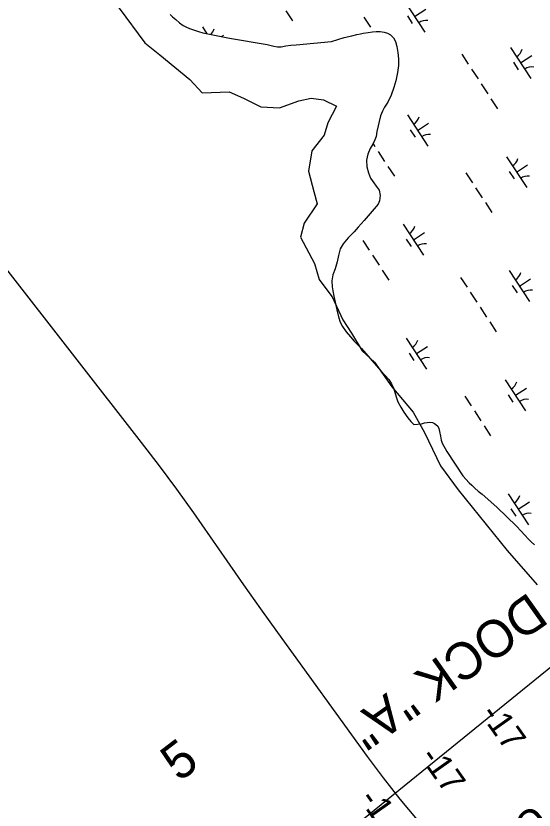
# Model space of a CAD drawing. Extents: x 3945642 to 3966284, y 206476 to 228921.
# Drawn here: x 3954881 to 3955580, y 219055 to 220127 of the extents above; entities that cross this region are included whole.
import ezdxf

# ---------------------------------------------------------------- set-up
doc = ezdxf.new("R2010")
doc.units = 0
for name, color, linetype in [('V-CHAN-NAID', 7, 'Continuous'), ('V-RIVR-EDGE', 7, 'Continuous'), ('V-RIVR-IDEN', 7, 'Continuous'), ('V-RIVR-RANG', 7, 'Continuous'), ('V-TOPO-MINR', 7, 'Continuous'), ('V-UTIL-IDEN', 7, 'Continuous'), ('V-UTIL-LINE', 7, 'Continuous'), ('V-WETL-SWMP', 7, 'Continuous')]:
    doc.layers.add(name, color=color, linetype=linetype)

msp = doc.modelspace()

# ---------------------------------------------------------------- linework, layer by layer
at = {"layer": 'V-RIVR-EDGE'}
msp.add_lwpolyline([(3954881.3, 220324.3), (3955054.6, 220090.4), (3955074.8, 220073.8), (3955115.2, 220040.5), (3955131.8, 220022.7), (3955168.6, 220023.9), (3955187.6, 220015.6), (3955211.3, 220003.7), (3955236.3, 220002.5), (3955262.4, 220012), (3955279, 220015.6), (3955295.6, 220013.2), (3955313.4, 220004.9), (3955301.6, 219982.4), (3955296.8, 219965.7), (3955280.2, 219944.4), (3955275.5, 219917.1), (3955282.6, 219889.8), (3955287.3, 219873.1), (3955269.5, 219847), (3955264.8, 219828), (3955283.8, 219792.4), (3955289.7, 219771), (3955300.4, 219756.8), (3955307.5, 219747.3), (3955321.8, 219716.4), (3955333.6, 219698.6), (3955347.9, 219674.9), (3955364.5, 219659.4), (3955388.2, 219626.2), (3955416.7, 219591.8), (3955432.2, 219564.5), (3955453.5, 219519.4), (3955477.3, 219487.3), (3955543.8, 219405.4), (3955584.1, 219359.1)], dxfattribs=at)
at = {"layer": 'V-TOPO-MINR'}
msp.add_lwpolyline([(3954493.5, 220264.9), (3955049.9, 219551), (3955073.9, 219519.7), (3955097.4, 219488.1), (3955120.3, 219456.1), (3955142.8, 219423.8), (3955165.2, 219391.3), (3955187.7, 219359), (3955210.6, 219326.8), (3955233.5, 219294.8), (3955354.8, 219127.6), (3955376.5, 219098.6), (3955398.9, 219070), (3955422.1, 219042.1)], dxfattribs=at)
at = {"layer": 'V-UTIL-LINE'}
msp.add_line((3954671.9, 218495), (3955749.6, 219367.2), dxfattribs=at)
at = {"layer": 'V-WETL-SWMP'}
for p, q in [((3955405.1, 220146.6), (3955432.5, 220104.7)), ((3955088.9, 220128.3), (3955092, 220125.3)), ((3955245.1, 220133.4), (3955253.9, 220120)), ((3955418.8, 220125.6), (3955433.8, 220135.5)), ((3955092, 220125.3), (3955096.4, 220121.5)), ((3955096.4, 220121.5), (3955101.6, 220117.3)), ((3955350.4, 220124.7), (3955359.1, 220111.3)), ((3955409, 220126.4), (3955415.6, 220116.4)), ((3955101.6, 220117.3), (3955106.4, 220113.7)), ((3955106.4, 220113.7), (3955110.1, 220111.7)), ((3955110.1, 220111.7), (3955114.9, 220109.6)), ((3955114.9, 220109.6), (3955120.5, 220107.5)), ((3955120.5, 220107.5), (3955126.9, 220105.4)), ((3955132.3, 220111.6), (3955138.3, 220102.5)), ((3955126.9, 220105.4), (3955132.8, 220103.6)), ((3955132.8, 220103.6), (3955168.9, 220096.4)), ((3955158, 220098.6), (3955161.1, 220100.6)), ((3955168.9, 220096.4), (3955219.8, 220087.9)), ((3955306.7, 220092), (3955323.7, 220097.2)), ((3955323.7, 220097.2), (3955334, 220099.6)), ((3955334, 220099.6), (3955340.6, 220101.3)), ((3955340.6, 220101.3), (3955345.8, 220102.5)), ((3955345.8, 220102.5), (3955349.5, 220103.1)), ((3955349.5, 220103.1), (3955355.9, 220103.9)), ((3955355.9, 220103.9), (3955361.8, 220104.8)), ((3955361.8, 220104.8), (3955367, 220105.3)), ((3955367, 220105.3), (3955372.2, 220105.4)), ((3955372.2, 220105.4), (3955377.8, 220104.7)), ((3955377.8, 220104.7), (3955382.3, 220103.2)), ((3955382.3, 220103.2), (3955386.2, 220100.9)), ((3955386.2, 220100.9), (3955390.1, 220096.9)), ((3955390.1, 220096.9), (3955392.8, 220091.8)), ((3955219.8, 220087.9), (3955228.6, 220085.5)), ((3955228.6, 220085.5), (3955233.9, 220084.8)), ((3955238.7, 220085), (3955244.9, 220086)), ((3955244.9, 220086), (3955251.5, 220087)), ((3955251.5, 220087), (3955258.7, 220087.7)), ((3955258.7, 220087.7), (3955306.7, 220092)), ((3955392.8, 220091.8), (3955394.8, 220085.2)), ((3955233.9, 220084.8), (3955238.7, 220085)), ((3955394.8, 220085.2), (3955396.2, 220077)), ((3955396.2, 220077), (3955397, 220068.7)), ((3955482.3, 220074.9), (3955491.1, 220061.5)), ((3955548.1, 220084), (3955575.5, 220042.2)), ((3955397, 220068.7), (3955396.8, 220059.6)), ((3955561.8, 220063.1), (3955576.9, 220073)), ((3955396.8, 220059.6), (3955395.5, 220050)), ((3955495.5, 220054.8), (3955504.3, 220041.4)), ((3955552.1, 220063.9), (3955558.7, 220053.9)), ((3955395.5, 220050), (3955393.3, 220039)), ((3955393.3, 220039), (3955390.8, 220030.1)), ((3955508.6, 220034.7), (3955517.4, 220021.4)), ((3955390.8, 220030.1), (3955387.2, 220019.5)), ((3955387.2, 220019.5), (3955382.6, 220010.2)), ((3955521.8, 220014.7), (3955530.6, 220001.3)), ((3955378, 220003.2), (3955375.2, 219998.1)), ((3955382.6, 220010.2), (3955378, 220003.2)), ((3955372.9, 219991.8), (3955367.7, 219970.4)), ((3955375.2, 219998.1), (3955372.9, 219991.8)), ((3955409, 219992.9), (3955436.4, 219951)), ((3955422.7, 219971.9), (3955437.7, 219981.8)), ((3955367.7, 219970.4), (3955366.8, 219963.7)), ((3955412.9, 219972.7), (3955419.5, 219962.7)), ((3955365.2, 219959.1), (3955362.3, 219953.7)), ((3955366.8, 219963.7), (3955365.2, 219959.1)), ((3955358.9, 219947.5), (3955355.4, 219940.2)), ((3955362.3, 219953.7), (3955358.9, 219947.5)), ((3955362.6, 219954.2), (3955365.1, 219950.3)), ((3955355.4, 219940.2), (3955353.8, 219932)), ((3955369.5, 219943.6), (3955378.3, 219930.2)), ((3955542.6, 219936.6), (3955570, 219894.8)), ((3955353.8, 219932), (3955354.4, 219922.9)), ((3955556.3, 219915.7), (3955571.3, 219925.6)), ((3955354.4, 219922.9), (3955356.5, 219914.9)), ((3955356.5, 219914.9), (3955359.4, 219907.8)), ((3955382.7, 219923.5), (3955391.4, 219910.1)), ((3955487.9, 219914.8), (3955496.7, 219901.4)), ((3955546.5, 219916.5), (3955553.1, 219906.5)), ((3955359.4, 219907.8), (3955363.5, 219901.1)), ((3955363.5, 219901.1), (3955366.8, 219896.8)), ((3955366.8, 219896.8), (3955370.8, 219891.2)), ((3955501, 219894.7), (3955509.8, 219881.3)), ((3955370.8, 219891.2), (3955372.2, 219884.4)), ((3955372.2, 219884.4), (3955371.5, 219876.9)), ((3955369.6, 219872.4), (3955350.5, 219850.6)), ((3955371.5, 219876.9), (3955369.6, 219872.4)), ((3955514.2, 219874.6), (3955523, 219861.3)), ((3955350.5, 219850.6), (3955342.7, 219841.6)), ((3955342.7, 219841.6), (3955337.3, 219835.1)), ((3955403.4, 219845.5), (3955430.8, 219803.7)), ((3955337.3, 219835.1), (3955329.2, 219827)), ((3955417.1, 219824.6), (3955432.2, 219834.4)), ((3955322.1, 219819.2), (3955318.3, 219812.2)), ((3955329.2, 219827), (3955322.1, 219819.2)), ((3955348.7, 219823.6), (3955357.5, 219810.3)), ((3955407.4, 219825.4), (3955414, 219815.3)), ((3955318.3, 219812.2), (3955316, 219803.1)), ((3955316, 219803.1), (3955314.4, 219794.7)), ((3955361.9, 219803.6), (3955370.7, 219790.2)), ((3955311.6, 219785.4), (3955308.5, 219777.1)), ((3955314.4, 219794.7), (3955311.6, 219785.4)), ((3955308.5, 219777.1), (3955306.8, 219769.2)), ((3955375, 219783.5), (3955383.8, 219770.1)), ((3955546.5, 219782.9), (3955573.9, 219741.1)), ((3955306.8, 219769.2), (3955307.4, 219761.2)), ((3955480.7, 219773.8), (3955489.5, 219760.4)), ((3955560.2, 219762), (3955575.3, 219771.9)), ((3955307.4, 219761.2), (3955308.3, 219755.8)), ((3955308.3, 219755.8), (3955309.9, 219748.6)), ((3955493.9, 219753.7), (3955502.6, 219740.4)), ((3955550.5, 219762.8), (3955557, 219752.8)), ((3955309.9, 219748.6), (3955313.9, 219730)), ((3955507, 219733.7), (3955515.8, 219720.3)), ((3955313.9, 219730), (3955315.8, 219720.6)), ((3955315.8, 219720.6), (3955318.3, 219713.4)), ((3955318.3, 219713.4), (3955321.5, 219707.3)), ((3955520.2, 219713.6), (3955528.9, 219700.2)), ((3955321.5, 219707.3), (3955326.4, 219700.3)), ((3955326.4, 219700.3), (3955332, 219693.7)), ((3955332, 219693.7), (3955337.3, 219687.9)), ((3955407.4, 219691.8), (3955434.8, 219650)), ((3955337.3, 219687.9), (3955347, 219677.6)), ((3955421.1, 219670.9), (3955436.1, 219680.7)), ((3955347, 219677.6), (3955373, 219647.8)), ((3955411.3, 219671.7), (3955417.9, 219661.6)), ((3955373, 219647.8), (3955383.9, 219635.8)), ((3955383.9, 219635.8), (3955387.6, 219630.3)), ((3955541, 219635.6), (3955568.4, 219593.7)), ((3955387.6, 219630.3), (3955390.2, 219624.8)), ((3955390.2, 219624.8), (3955391.5, 219620.1)), ((3955391.5, 219620.1), (3955393.8, 219612.5)), ((3955544.9, 219615.4), (3955551.5, 219605.4)), ((3955554.7, 219614.7), (3955569.7, 219624.5)), ((3955393.8, 219612.5), (3955396.3, 219605.7)), ((3955396.3, 219605.7), (3955400.1, 219598.8)), ((3955486.3, 219613.7), (3955495, 219600.3)), ((3955400.1, 219598.8), (3955404.2, 219591.8)), ((3955499.4, 219593.6), (3955508.2, 219580.3)), ((3955404.2, 219591.8), (3955409.4, 219584.4)), ((3955409.4, 219584.4), (3955413.8, 219579.4)), ((3955413.8, 219579.4), (3955417.9, 219575.5)), ((3955417.9, 219575.5), (3955428.1, 219576)), ((3955428.1, 219576), (3955432, 219577.5)), ((3955432, 219577.5), (3955435.8, 219578.2)), ((3955435.8, 219578.2), (3955439.5, 219578.5)), ((3955439.5, 219578.5), (3955442.8, 219577.8)), ((3955442.8, 219577.8), (3955445.4, 219576.8)), ((3955445.4, 219576.8), (3955447.4, 219575.3)), ((3955447.4, 219575.3), (3955449.9, 219572.9)), ((3955449.9, 219572.9), (3955451.3, 219570)), ((3955512.6, 219573.6), (3955521.3, 219560.2)), ((3955451.3, 219570), (3955452.4, 219565.9)), ((3955452.4, 219565.9), (3955453.7, 219559.4)), ((3955453.7, 219559.4), (3955454.6, 219554.3)), ((3955454.6, 219554.3), (3955455.8, 219550.2)), ((3955455.8, 219550.2), (3955462.4, 219538.7)), ((3955462.4, 219538.7), (3955483.8, 219506.1)), ((3955483.8, 219506.1), (3955492.5, 219496.5)), ((3955492.5, 219496.5), (3955495.8, 219493.5)), ((3955495.8, 219493.5), (3955499.9, 219489.5)), ((3955499.9, 219489.5), (3955504.6, 219485.3)), ((3955504.6, 219485.3), (3955509.7, 219481.2)), ((3955509.7, 219481.2), (3955529.6, 219463.6)), ((3955544.9, 219481.9), (3955572.3, 219440)), ((3955558.6, 219461), (3955573.6, 219470.8)), ((3955529.6, 219463.6), (3955556.3, 219438.1)), ((3955548.8, 219461.7), (3955555.4, 219451.7)), ((3955556.3, 219438.1), (3955562.2, 219431.7)), ((3955562.2, 219431.7), (3955567.3, 219425.9)), ((3955567.3, 219425.9), (3955572.3, 219420.6)), ((3955572.3, 219420.6), (3955576.1, 219416.9)), ((3955576.1, 219416.9), (3955580.6, 219412.9))]:
    msp.add_line(p, q, dxfattribs=at)
for centre, start, end in [((3955434.1, 220102.7), 82.4574, 124.0011), ((3955131.1, 220114), 314.8782, 344.0011), ((3955546.9, 220086.3), 302.4575, 344.0011), ((3955577.2, 220040.1), 82.4574, 124.0011), ((3955407.8, 219995.2), 302.4575, 344.0011), ((3955438, 219949), 82.4574, 124.0011), ((3955541.3, 219939), 302.4575, 344.0011), ((3955571.6, 219892.7), 82.4574, 124.0011), ((3955402.2, 219847.8), 302.4575, 344.0011), ((3955432.5, 219801.6), 82.4574, 124.0011), ((3955545.3, 219785.3), 302.4575, 344.0011), ((3955575.5, 219739.1), 82.4574, 124.0011), ((3955406.1, 219694.1), 302.4575, 344.0011), ((3955436.4, 219647.9), 82.4574, 124.0011), ((3955539.7, 219637.9), 302.4575, 344.0011), ((3955570, 219591.7), 82.4574, 124.0011), ((3955543.7, 219484.2), 302.4575, 344.0011), ((3955573.9, 219438), 82.4574, 124.0011)]:
    msp.add_arc(centre, 17.6, start, end, dxfattribs=at)

# ---------------------------------------------------------------- texts
at = {"layer": 'V-CHAN-NAID'}
msp.add_text('DOCK "A"', height=50, rotation=215.2931, dxfattribs=at).set_placement((3955573.2, 219350.1))
at = {"layer": 'V-RIVR-IDEN'}
msp.add_text('5', height=50, rotation=37.4579, dxfattribs=at).set_placement((3955101, 219092.2))
at = {"layer": 'V-RIVR-RANG'}
for s, p in [('-17', (3955506.4, 219184.7)), ('-17', (3955424.8, 219126.9)), ('-14', (3955342.8, 219069.9))]:
    msp.add_text(s, height=33.5, rotation=305.3228, dxfattribs=at).set_placement(p)
at = {"layer": 'V-UTIL-IDEN'}
msp.add_text('SOUTHERN NATURAL GAS SUPPLY PIPELINE', height=42, rotation=219.5731, dxfattribs=at).set_placement((3955921.7, 219347.2))

doc.saveas('drawing.dxf')
